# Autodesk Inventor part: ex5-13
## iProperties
Author: Administrator
Created: 2001-09
Part Number: ex5-13
Document SubType Name: Modeling
Designer: Administrator
Control State: 0
Master: False
Checked Out: False
PropertySet Name: Design Tracking Control
Length Units: 11272
Angle Units: 11279
Time Units: 11290
Mass Units: 11286
Shininess: 3
Angle Display Precision: 2
Document Length Units: 11272
Document Angle Units: 11286
Document Time Units: 11279
Document Mass Units: 11290
Document Length Units Precision: 3
Document Angle Units Precision: 2
Compacted: False
PropertySet Name: _Private Model Information
Density: 0.0
Volumn: 0.0
Area: 0.0
PropertySet Name: Model Information
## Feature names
1. Revolution1
2. Hole1
3. Circular Pattern1
